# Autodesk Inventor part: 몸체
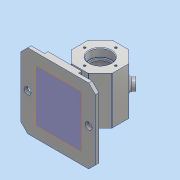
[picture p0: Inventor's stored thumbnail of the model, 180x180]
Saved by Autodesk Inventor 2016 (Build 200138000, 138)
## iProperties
Created: 2018-06
Part Number: 몸체
Material: 알루미늄 6061
Document SubType Name: Modeling
Designer: 605-11
Density: 2.7 g/cm^3
Appearance: 알루미늄 - 평지
Mass: 551.997 g
Surface Area: 601.935 cm^2
Volume: 204.443 cm^3
Author: 605-11
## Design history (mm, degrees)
sketch "스케치1"
  geometry: L1 (30, -12.426)-(12.426, -30); L2 (12.426, -30)-(-12.426, -30); L3 (-12.426, -30)-(-30, -12.426); L4 (-30, -12.426)-(-30, 12.426); L5 (-30, 12.426)-(-12.426, 30); L6 (-12.426, 30)-(12.426, 30); L7 (12.426, 30)-(30, 12.426); L8 (30, 12.426)-(30, -12.426); L9 (0, 0)-(-12.426, 30); L10 (0, 0)-(0, 30); L11 (0, 0)-(12.426, 30); 1 further point
  constraints: 22 end point, 2 point on line, 1 coincident, 1 midpoint, 1 vertical, 1 vertical alignment, 17 other
  dimensions: "d0" = 60 distance between parallel lines of L8 L4; "d1" = 22.5 deg angle of L10 L9; "d2" = 45 deg angle of L11 L9
extrude "돌출1" new body sketch "스케치1" stored distance "d3" = 70; taper "d4" = 0 deg
sketch "스케치2"
  geometry: L1 (0, 35)-(16, 35); L2 (16, 35)-(16, 23.3); L3 (15.7, 23)-(0, 23); L4 (0, 23)-(0, 35); L5 (0, 23)-(14, 23); L6 (14, 23)-(14, 20); L7 (14, 20)-(0, 20); L8 (0, 20)-(0, 23); L9 (0, 20)-(22, 20); L10 (25, 17)-(25, -17); L11 (22, -20)-(0, -20); L12 (0, -20)-(0, 20); L13 (0, -20)-(14, -20); L14 (14, -20)-(14, -23); L15 (14, -23)-(0, -23); L16 (0, -23)-(0, -20); L17 (0, -23)-(15.7, -23); L18 (16, -23.3)-(16, -35); L19 (16, -35)-(0, -35); L20 (0, -35)-(0, -23); L21 (12.426, 35)-(-12.426, 35) reference; A1 r 0.3 centre (15.7, 23.3) between (15.7, 23) and (16, 23.3); A2 r 0.3 centre (15.7, -23.3) between (16, -23.3) and (15.7, -23); A3 r 3 centre (22, -17) between (22, -20) and (25, -17); A4 r 3 centre (22, 17) between (25, 17) and (22, 20); 6 further points
  constraints: 40 end point, 10 parallel, 8 point on circle, 8 point on line, 8 tangent, 5 horizontal, 5 perpendicular, 4 centre point, 2 equal radius, 1 coincident, 1 midpoint
  dimensions: "d5" = 12 distance of L1.end point (16, 23); "d6" = 16 distance of L1.start L1.end; "d7" = 3 distance of L5.end L6.end; "d8" = 14 distance of L3.end L5.end; "d9" = 40 distance of point (25, 20) point (25, -20); "d10" = 25 distance of L7.end point (25, 20); "d11" = 3 distance of L13.end L14.end; "d12" = 14 distance of L11.end L13.end; "d13" = 12 distance of point (16, -23) L18.end; "d14" = 16 distance of L15.end point (16, -23); "d15" = 0.3 radius of A1; "d16" = 3 radius of A3
revolve "회전1" sketch "스케치2" stored, may be unused: angle "d17" = 90 deg
chamfer "모따기1" distance "d18" = 1; stored, may be unused: second distance "d19" = 2, angle "d20" = 45 deg
sketch "스케치3"
  geometry: L1 (-24.853, 70)-(0, 70) reference; C1 r 8 at (-12.426, 35); 2 further points
  constraints: 1 centre point, 1 midpoint, 1 vertical alignment
  dimensions: "d21" = 35 distance from line of L1 C1.centre; "d22" = 16 diameter of C1
extrude "돌출2" join sketch "스케치3" distance "d23" = 7; taper "d24" = 0 deg
fillet "모깎기1" dims "d25" = 3
sketch "스케치4"
  geometry: C1 r 4 at (0, 0); 1 further point
  constraints: 1 centre point, 1 coincident
  dimensions: "d26" = 8 diameter of C1
extrude "돌출3" cut sketch "스케치4" stored distance "d27" = 7; taper "d28" = 0 deg; dims "d5" = 12, "d6" = 16, "d7" = 3, "d8" = 14, "d9" = 40, "d10" = 25, "d11" = 3, "d12" = 14, "d13" = 12, "d14" = 16, "d15" = 0.3, "d16" = 3, "d31" = 45 deg
chamfer "모따기2" distance "d29" = 1; stored, may be unused: second distance "d30" = 2, angle "d31" = 45 deg
sketch "스케치5" dims "d32" = 46
  geometry: 3 further points
  constraints: 2 vertical alignment, 1 coincident, 2 other
hole "구멍1" sketch "스케치5" at (0, 23) diameter "d33" = 3.242; stored, may be unused: countersink angle "d37" = 90 deg, drill point angle "d39" = 118 deg; dims "d34" = 8, "d35" = 4, "d36" = 2, "d38" = 10
fillet "모깎기2" dims "d43" = 1
node "작업 평면1"
sketch "스케치6"
  geometry: L1 (12.012, -35)-(-12.012, -35) reference; L2 (30, -35)-(30, 35) reference; L3 (-30, 35)-(-30, -35) reference; L4 (-12.012, 35)-(12.012, 35) reference; L5 (45, -55)-(-45, -55); L6 (-55, -45)-(-55, 45); L7 (-45, 55)-(45, 55); L8 (55, 45)-(55, -45); L9 (55, -55)-(-55, 55); L10 (-55, -55)-(55, 55); L11 (55, -45)-(45, -55); L12 (55, 45)-(45, 55); L13 (-45, 55)-(-55, 45); L14 (-55, -45)-(-45, -55); 1 further point
  constraints: 20 end point, 8 point on line, 2 midpoint, 2 parallel, 1 horizontal, 1 perpendicular
  dimensions: "d45" = 110 distance of L9.start L10.start; "d46" = 110 distance of L10.start L9.end; "d47" = 10 distance of L8.end L9.start; "d48" = 10 distance of L5.start L9.start (= d47); "d49" = 10 distance of L8.start L10.end (= d47); "d50" = 10 distance of L7.end L10.end (= d49); "d51" = 10 distance of L7.start L9.end (= d47); "d52" = 10 distance of L6.end L9.end (= d51); "d53" = 10 distance of L6.start L10.start (= d47); "d54" = 10 distance of L5.end L10.start (= d53)
extrude "돌출4" join sketch "스케치6" distance "d55" = 5; taper "d56" = 0 deg
sketch "스케치7"
  geometry: L1 (-25, 55)-(25, 55); L2 (25, 55)-(25, -55); L3 (25, -55)-(-25, -55); L4 (-25, -55)-(-25, 55); L5 (-25, 55)-(25, -55); L6 (25, 55)-(-25, -55); L7 (55, 45)-(55, -45) reference; 1 further point
  constraints: 12 end point, 2 midpoint, 2 parallel, 1 horizontal, 1 perpendicular
  dimensions: "d57" = 110 distance of L1.end L2.end; "d58" = 30 distance between parallel lines of L7 L2
extrude "돌출5" join sketch "스케치7" distance "d59" = 5; taper "d60" = 0 deg
sketch "스케치8"
  geometry: L1 (0, 19)-(0, -19); L2 (-5, 19)-(-5, -19); L3 (5, -19)-(5, 19); L4 (-55, 45)-(-55, -45) reference; L5 (45, -55)-(-45, -55) reference; A1 r 5 centre (0, 19) between (5, 19) and (-5, 19); A2 r 5 centre (0, -19) between (-5, -19) and (5, -19); 2 further points
  constraints: 8 end point, 4 point on circle, 4 tangent, 2 centre point, 1 midpoint, 1 parallel, 1 vertical
  dimensions: "d61" = 55 distance from line of L4 point (0, 0); "d62" = 38 distance of L1.start L1.end; "d63" = 55 distance from line of L5 point (0, 0); "d64" = 5 radius of A1
extrude "돌출6" join sketch "스케치8" stored distance "d65" = 5; taper "d66" = 0 deg
fillet "모깎기3" dims "d67" = 2
sketch "스케치9"
  geometry: L1 (-55, -45)-(-55, 45) reference; C1 r 5 at (-45, 0); 1 further point
  constraints: 1 centre point, 1 horizontal alignment
  dimensions: "d70" = 10 distance from line of L1 C1.centre; "d71" = 10 diameter of C1
extrude "돌출7" cut sketch "스케치9" stored distance "d72" = 5; taper "d73" = 0 deg
node "작업 평면2"
sketch "스케치10"
  geometry: L1 (-12.012, 35)-(12.012, 35) reference; 2 further points
  constraints: 1 coincident, 1 other
  dimensions: "d75" = 35 distance from line of point (0, 0) L1
feature "엠보싱1" sketch "스케치10" dims "d0" = 60, "d1" = 22.5 deg, "d2" = 45 deg, "d5" = 12, "d6" = 16, "d7" = 3, "d8" = 14, "d9" = 40, "d10" = 25, "d11" = 3, "d12" = 14, "d13" = 12, "d14" = 16, "d15" = 0.3, "d16" = 3, "d76" = 0.5, "d77" = 0
node "솔리드1"
pattern_circular "원형 패턴1" dims angle "d41" = 360 deg
mirror "대칭1"
mirror "대칭2"
other parameters: "d44" = -62, "d74" = 52.25
